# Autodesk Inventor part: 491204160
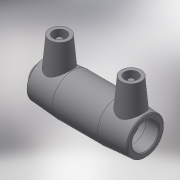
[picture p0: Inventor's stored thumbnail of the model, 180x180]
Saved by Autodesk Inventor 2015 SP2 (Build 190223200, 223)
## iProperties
Created: 2017-06
Part Number: 491204160
Material: Generic
Description: PLASSON END CAP 160
Document SubType Name: Modeling
Designer: KIM
Mass: 38.9236 g
Surface Area: 152.394 cm^2
Volume: 38.9236 cm^3
Density: 1 g/cm^3
Appearance: Default
Author: KIM
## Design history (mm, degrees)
derived "491204.ipt"
feature "Solid1::491204.ipt"
tag "TaggingFeature1"
body "Solid1"
other parameters: "d0" = 195, "d2" = 194, "d3" = 93, "d4" = 65.25, "d5" = 174.6, "d6" = 152, "d8" = 168 deg, "d10" = 37.2, "d11" = 12.4, "d13" = 208.8, "d14" = 17.6296, "d15" = 93, "d16" = 93, "d17" = 152, "d19" = 3.52592, "d20" = 168 deg, "d22" = 182.36, "d23" = 194, "d24" = 176.8892, "d25" = 135 deg, "d26" = 93.96, "d27" = 135 deg, "d29" = 105, "d30" = 15, "d31" = 83.52, "d34" = 5 deg, "d35" = 15, "d39" = 5 deg, "d41" = 4, "d42" = 14, "d43" = 0, "d45" = 4, "d46" = 14, "d47" = 0, "d48" = 261, "d49" = 1, "d51" = 128, "d52" = 4.698, "d53" = 176, "d54" = 4.698, "d56" = 16, "d57" = 4.8, "d60" = 39.15, "d61" = 3.2, "d63" = 261, "d64" = 1, "d66" = 128, "d67" = 32, "d68" = 176, "d69" = 5.22, "d70" = 0, "d71" = 4.698, "d72" = 3, "d73" = 0, "d74" = 26.97, "d75" = 8.99, "d76" = 3, "d77" = 0, "L_" = 261, "L_1" = 93, "D_" = 194, "A_" = 105, "d_2" = 12, "L_0" = 195, "d55" = 16
